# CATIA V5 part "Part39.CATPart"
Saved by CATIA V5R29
Part number: pan head cross recess screw_iso_ISO 7045 - M3 x 4 - Z - 4N
Revision: ANY
Definition: UNKNOWN
Nomenclature: pan head cross recess screw_iso_ISO 7045 - M3 x 4 - Z - 4N
Source: Unknown
Bounding box of the stored display mesh (mm): x 0.046 to 6.4, y -2.79 to 2.79, z -2.8 to 2.8
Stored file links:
  C:\Users\Administrator\Desktop\프로젝트\Gripper\Part39.CATPart
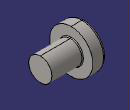
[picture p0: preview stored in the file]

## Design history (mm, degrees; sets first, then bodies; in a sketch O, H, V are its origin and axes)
Body1 "RecessCore" (main body)
  Solid1: solid without history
